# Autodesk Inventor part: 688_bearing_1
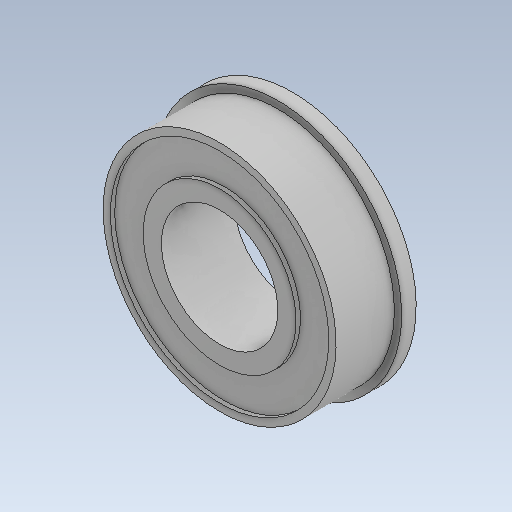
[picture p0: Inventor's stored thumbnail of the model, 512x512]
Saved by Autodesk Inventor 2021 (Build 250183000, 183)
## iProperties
Created: 2026-10
Part Number: 688_bearing_1
Material: Generic
Document SubType Name: Modeling
Designer: hp
Density: 1 g/cm^3
Appearance: Default
Author: hp
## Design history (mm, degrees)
feature "Body1"
body "Solid1"
